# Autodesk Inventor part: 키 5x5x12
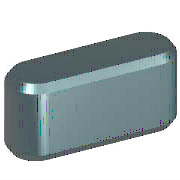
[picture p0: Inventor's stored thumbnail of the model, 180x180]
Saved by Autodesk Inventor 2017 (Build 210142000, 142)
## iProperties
IsCustomPart: 1
Created: 2012-02
Part Number: 키 5x5x12
Material: 강철, 연강
Description: 키 및 해당 키홈
Document SubType Name: Modeling
Standard: KS B 1311
Designer: mduedu
Standards Organization: KS
Language: ko-KR
Size Designation: 5 x 5 x 12
Categories: <MemberInstance><Categories><Category DisplayName="샤프트 부품" InternalName="7f7aeb1f-a693-4053-b835-cee3144e0d98" Mnemonic="SHFT"><Category DisplayName="키" Interna
Density: 1 g/cm^3
Appearance: 노란색
Author: mduedu
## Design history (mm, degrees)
workplane "Work Plane1"
workplane "Work Plane2"
sketch "스케치1"
  geometry: L1 (2.5, 2.5)-(9.5, 2.5); L2 (9.5, -2.5)-(2.5, -2.5); L3 (0, 9.4)-(0, -7.4) reference; L4 (-5, 0)-(30, 0) reference; L5 (12, 0)-(12, 7); A1 r 2.5 centre (2.5, 0) between (2.5, 2.5) and (2.5, -2.5); A2 r 2.5 centre (9.5, 0) between (9.5, -2.5) and (9.5, 2.5)
  constraints: 6 end point, 5 point on circle, 4 tangent, 3 point on line, 2 centre point, 1 horizontal, 1 parallel, 1 perpendicular
  dimensions: "d0" = 2.5 radius of A1 (= 0.5 x PB); "d13" = 2.5 radius of A2 (= 0.5 x PB); "d14" = 12 distance between parallel lines of L5 L3 (= NLG)
extrude "본체1" new body sketch "스케치1" taper "d3" = 0 deg; stored distance "d4" = 10
workplane "Work Plane3"
body "Solid1"
chamfer "모따기1" distance "d8" = 0.4 (= PHH); stored, may be unused: second distance "d9" = 0.4 (= PHH), angle "d15" = 45 deg
other parameters: "d1" = -3 (= -PNT), "d2" = 2 (= PH - PNT), "NLG" = 12 [user parameter; used in 3 equation terms], "PB" = 5 [user parameter; used in 2 equation terms], "PNT" = 3 [user parameter; used in 2 equation terms], "PH" = 5 [user parameter; used in 1 equation term], "PHH" = 0.4 [user parameter; used in 2 equation terms], "d10" = 0, "d16" = 0, "d17" = 0, "d18" = 0, "WDMIN" = 12 [user parameter], "PLB2" = 12 (= NLG) [user parameter], "WDMAX" = 17 [user parameter], "PLB1" = 12 (= NLG) [user parameter], "RR" = 0.16 [user parameter], "PUEB" = 2.3 [user parameter]
